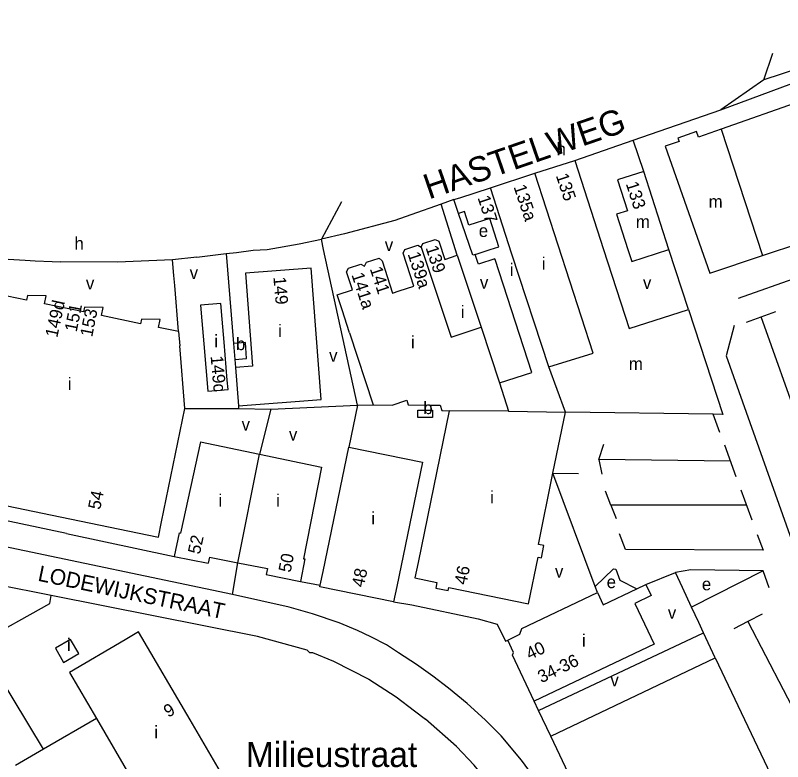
# Model space of a CAD drawing. Extents: x 157699 to 159683, y 381451 to 383293.
# Drawn here: x 159180.6 to 159425.3, y 382736.7 to 382974.7 of the extents above; entities that cross this region are included whole.
import ezdxf

# ---------------------------------------------------------------- set-up
doc = ezdxf.new("R2010")
doc.units = 0
for name, color, linetype in [('BLT_Basislijn', 7, 'Continuous'), ('BLT_Bebouwing', 7, 'Continuous'), ('BLT_Bebouwing_beschrifting', 7, 'Continuous'), ('BLT_Centroide', 7, 'Continuous'), ('BLT_Huisnummer', 7, 'Continuous'), ('BLT_Huisnummer_reeks', 7, 'Continuous'), ('BLT_Onderverdeling_panden', 7, 'Continuous'), ('BLT_Straatnaam', 7, 'Continuous'), ('BLT_Straatnaam_hoofdweg', 7, 'Continuous'), ('BLT_Vlakafsluiter', 7, 'Continuous')]:
    doc.layers.add(name, color=color, linetype=linetype)

msp = doc.modelspace()

# ---------------------------------------------------------------- linework, layer by layer
at = {"layer": 'BLT_Basislijn'}
for p, q in [((159405.59, 382944.56), (159433.38, 382954.9)), ((159419.3, 382954.14), (159405.59, 382944.56)), ((159377.66, 382934.89), (159405.59, 382944.56)), ((159358.99, 382928.43), (159377.66, 382934.89)), ((159381.06, 382924.92), (159377.66, 382934.89)), ((159316.43, 382914.45), (159306.72, 382911.03)), ((159320.48, 382915.92), (159316.43, 382914.45)), ((159321.51, 382898.15), (159316.43, 382914.45)), ((159271.08, 382901.86), (159278.18, 382903.33)), ((159395.3, 382880.89), (159389.05, 382899.99)), ((159238.5, 382897.55), (159230.71, 382896.67)), ((159238.5, 382897.55), (159247.77, 382898.73)), ((159247.77, 382898.73), (159251.13, 382899.05)), ((159247.77, 382898.73), (159250.17, 382870.05)), ((159411.28, 382884.48), (159430.54, 382891.32)), ((159232.61, 382873.85), (159231.39, 382888.49)), ((159418.48, 382878.56), (159423.16, 382880.28)), ((159413.8, 382876.85), (159418.48, 382878.56)), ((159444.29, 382805.9), (159418.48, 382878.56)), ((159250.58, 382864.94), (159250.77, 382862.38)), ((159289.75, 382850.37), (159294.66, 382850.46)), ((159234.65, 382849.3), (159251.75, 382849.31)), ((159251.72, 382850.16), (159251.75, 382849.31)), ((159251.75, 382849.31), (159262.09, 382849.15)), ((159262.09, 382849.15), (159258.5, 382834.72)), ((159262.09, 382849.15), (159289.75, 382850.37)), ((159289.75, 382850.37), (159286.99, 382837.02)), ((159405.33, 382841.71), (159403.13, 382847.47)), ((159366.66, 382833.1), (159368.33, 382837.98)), ((159410.49, 382827.48), (159406.9, 382837.58)), ((159408.69, 382832.53), (159366.66, 382833.1)), ((159366.66, 382833.1), (159367.7, 382828.4)), ((159352.07, 382828.68), (159360.16, 382828.55)), ((159365.53, 382792.56), (159352.07, 382828.68)), ((159370.57, 382818.5), (159368.87, 382823)), ((159415.56, 382813.69), (159412.12, 382823.31)), ((159413.84, 382818.5), (159370.57, 382818.5)), ((159370.57, 382818.5), (159372.2, 382814.21)), ((159249.82, 382790.04), (159157.68, 382809.27)), ((159249.82, 382790.04), (159251.53, 382800.15)), ((159381.72, 382793.17), (159391.11, 382797.04)), ((159393.35, 382792.24), (159391.11, 382797.04)), ((159419.07, 382797.56), (159396.27, 382785.95)), ((159421.07, 382792.13), (159419.07, 382797.56)), ((159271.49, 382794.17), (159277.85, 382792.96)), ((159192.02, 382789.67), (159172.64, 382793.53)), ((159366.25, 382790.62), (159365.53, 382792.56)), ((159396.27, 382785.95), (159393.35, 382792.24)), ((159267.9, 382785.97), (159249.82, 382790.04)), ((159398.56, 382781.04), (159396.27, 382785.95)), ((159418.75, 382783.71), (159414.23, 382781.36)), ((159400.07, 382777.8), (159398.56, 382781.04)), ((159414.23, 382781.36), (159409.71, 382779.02)), ((159414.23, 382781.36), (159441.99, 382727.89)), ((159347.48, 382753.01), (159400.07, 382777.8)), ((159403.79, 382769.82), (159400.07, 382777.8)), ((159189.49, 382740.66), (159169.07, 382774.57)), ((159347.48, 382753.01), (159346.07, 382755.99)), ((159307.89, 382752.96), (159311.44, 382750.26)), ((159351.37, 382744.8), (159347.48, 382753.01)), ((159206.41, 382750.47), (159189.49, 382740.66)), ((159189.49, 382740.66), (159180.65, 382735.54))]:
    msp.add_line(p, q, dxfattribs=at)
for points in [[(159482.05, 382974.66), (159419.3, 382954.14)], [(159306.72, 382911.03), (159301.59, 382909.22), (159285.55, 382904.97), (159278.18, 382903.33)], [(159327.25, 382898.44), (159326.49, 382898.2), (159321.91, 382911.53)], [(159251.13, 382899.05), (159256.38, 382899.84), (159260.85, 382900), (159271.08, 382901.86)], [(159289.75, 382850.37), (159278.9, 382900), (159278.18, 382903.33)], [(159174.06, 382897.31), (159178.29, 382896.96), (159183.66, 382896.59), (159186.91, 382896.41)], [(159186.91, 382896.41), (159192.29, 382896.17), (159194.9, 382896.09)], [(159230.71, 382896.67), (159213.14, 382896.01), (159194.9, 382896.09)], [(159231.39, 382888.49), (159231.13, 382891.69), (159230.71, 382896.67)], [(159409.89, 382875.79), (159407.36, 382866.13), (159430.53, 382800.86), (159435.45, 382802.6)], [(159196.92, 382809.44), (159162.12, 382816.84), (159164.52, 382828.13)], [(159196.92, 382809.44), (159231.19, 382802.16)], [(159417.25, 382809.12), (159419.08, 382804.13), (159375.19, 382804.37), (159373.3, 382809.31)], [(159365.53, 382792.56), (159371.42, 382798.18), (159372.14, 382798.11), (159373.36, 382794.55), (159378.78, 382791.77)], [(159419.07, 382797.56), (159396.05, 382797.87), (159391.11, 382797.04)], [(159169.07, 382774.57), (159191.56, 382787.19), (159192.02, 382789.67)], [(159274.43, 382771.53), (159273.7, 382772.23), (159257.81, 382776.61), (159192.02, 382789.67)], [(159301.24, 382787.64), (159307.05, 382786.68), (159328.25, 382782.21), (159334.31, 382780.6), (159336.95, 382775.15), (159337.62, 382775.47)], [(159330.47, 382750), (159324.69, 382755.29), (159318.76, 382760.18), (159313.79, 382763.99), (159308.48, 382767.72), (159302.77, 382771.4), (159298.94, 382773.91), (159294.01, 382776.56), (159289.75, 382778.54), (159283.84, 382780.98), (159275.31, 382783.83), (159267.9, 382785.97)], [(159274.43, 382771.53), (159275.35, 382771.52), (159282.09, 382768.77), (159293.32, 382763.04), (159302.06, 382757.38), (159307.89, 382752.96)], [(159328.36, 382733.92), (159326.98, 382735.56), (159321.31, 382741.52), (159311.44, 382750.26)], [(159371.1, 382685.16), (159365.19, 382697.64), (159361.34, 382705.19), (159358.24, 382711.23), (159354.7, 382717.43), (159350.72, 382724.13), (159346.42, 382731.2), (159342.06, 382737.2), (159335.54, 382744.96), (159330.47, 382750)]]:
    msp.add_lwpolyline(points, dxfattribs=at)
at = {"layer": 'BLT_Bebouwing'}
for p, q in [((159471.87, 382961.72), (159405.77, 382938.41)), ((159387.82, 382932.93), (159402.1, 382892.49)), ((159346.28, 382924.3), (159358.99, 382928.43)), ((159332.1, 382919.7), (159346.28, 382924.3)), ((159322.36, 382916.53), (159332.1, 382919.7)), ((159320.48, 382915.92), (159322.36, 382916.53)), ((159331.89, 382909.88), (159325.26, 382907.72)), ((159334.81, 382900.9), (159331.89, 382909.88)), ((159418.86, 382898.09), (159434.65, 382903.36)), ((159402.1, 382892.49), (159418.86, 382898.09)), ((159184.15, 382883.86), (159171.78, 382886.41)), ((159184.46, 382885.38), (159184.15, 382883.86)), ((159329.21, 382875.22), (159334.98, 382857.47)), ((159232.61, 382873.85), (159232.99, 382869.32)), ((159287.19, 382873.46), (159294.66, 382850.46)), ((159248.16, 382858.39), (159247.14, 382870.43)), ((159253.93, 382870.35), (159250.17, 382870.05)), ((159254.34, 382865.24), (159253.93, 382870.35)), ((159234.65, 382849.3), (159232.99, 382869.32)), ((159250.58, 382864.94), (159254.34, 382865.24)), ((159352.07, 382828.68), (159356.06, 382848.18)), ((159239.58, 382838.68), (159233.29, 382809.56)), ((159239.58, 382838.68), (159258.5, 382834.72)), ((159258.5, 382834.72), (159278.19, 382830.63)), ((159278.19, 382830.63), (159272.45, 382801.43)), ((159169.6, 382819.99), (159197.9, 382814.15)), ((159197.9, 382814.15), (159226.2, 382808.31)), ((159232.81, 382809.64), (159231.19, 382802.16)), ((159232.81, 382809.64), (159233.29, 382809.56)), ((159231.19, 382802.16), (159242.05, 382800.01)), ((159242.47, 382801.95), (159242.05, 382800.01)), ((159242.47, 382801.95), (159251.53, 382800.15)), ((159251.53, 382800.15), (159261.02, 382798.26)), ((159272.92, 382801.35), (159271.49, 382794.17)), ((159272.45, 382801.43), (159272.92, 382801.35)), ((159261.02, 382798.26), (159260.6, 382796.34)), ((159260.6, 382796.34), (159271.49, 382794.17)), ((159277.74, 382792.46), (159277.85, 382792.96)), ((159301.24, 382787.64), (159277.74, 382792.46)), ((159378.78, 382791.77), (159381.72, 382793.17)), ((159384.35, 382774.19), (159346.07, 382755.99)), ((159351.37, 382744.8), (159403.79, 382769.82)), ((159206.41, 382750.47), (159219.18, 382728.66)), ((159379.52, 382685.92), (159351.37, 382744.8))]:
    msp.add_line(p, q, dxfattribs=at)
for points in [[(159405.77, 382938.41), (159398.5, 382935.85), (159397.9, 382937.59), (159391.95, 382935.48), (159392.28, 382934.49), (159387.82, 382932.93)], [(159358.99, 382928.43), (159368.23, 382900), (159376.42, 382874.78), (159395.3, 382880.89)], [(159381.06, 382924.92), (159372.67, 382922.21), (159375.82, 382912.33), (159372.35, 382911.22)], [(159389.05, 382899.99), (159381.06, 382924.92)], [(159321.91, 382911.53), (159320.48, 382915.92)], [(159325.26, 382907.72), (159323.82, 382912.15), (159321.91, 382911.53)], [(159372.35, 382911.22), (159375.99, 382900), (159377.25, 382896.15), (159389.05, 382899.99)], [(159310.06, 382900.8), (159310.59, 382901.94), (159314.47, 382903.21), (159315.67, 382902.62), (159317.57, 382896.85), (159321.51, 382898.15)], [(159304.24, 382898.84), (159304.84, 382900.04), (159308.93, 382901.38), (159310.06, 382900.8)], [(159327.25, 382898.44), (159332.05, 382900), (159334.81, 382900.9)], [(159283.26, 382885.55), (159288.09, 382887.11), (159286.22, 382892.86), (159286.83, 382894.06), (159290.72, 382895.32), (159291.99, 382894.68), (159292.63, 382895.92), (159296.65, 382897.23), (159297.54, 382896.43), (159300.89, 382886.11), (159303.05, 382886.82)], [(159303.05, 382886.82), (159307.66, 382888.31), (159304.24, 382898.84)], [(159321.51, 382898.15), (159329.21, 382875.22)], [(159333.61, 382896.77), (159333.52, 382897.06), (159328.26, 382895.35), (159328.08, 382895.89), (159327.25, 382898.44)], [(159334.98, 382857.47), (159345.29, 382860.82), (159333.61, 382896.77)], [(159251.72, 382850.16), (159278.12, 382852.23), (159274.88, 382894.07), (159254, 382892.47), (159256.24, 382862.81), (159250.77, 382862.38)], [(159232.61, 382873.85), (159226.2, 382875.17), (159226.72, 382877.69), (159220.8, 382877.76), (159220.49, 382876.35), (159208.01, 382878.93), (159208.53, 382881.46), (159202.62, 382881.62), (159202.33, 382880.11), (159189.86, 382882.68), (159190.37, 382885.19), (159184.46, 382885.38)], [(159287.19, 382873.46), (159284.81, 382880.79), (159283.26, 382885.55)], [(159247.14, 382870.43), (159246.51, 382877.81), (159246.08, 382882.79), (159239.6, 382882.22)], [(159239.6, 382882.22), (159240.02, 382877.24), (159240.65, 382869.94)], [(159395.3, 382880.89), (159406.24, 382847.42), (159403.13, 382847.47)], [(159250.17, 382870.05), (159250.58, 382864.94)], [(159240.65, 382869.94), (159241.94, 382854.83), (159248.42, 382855.37), (159248.16, 382858.39)], [(159250.77, 382862.38), (159251.72, 382850.16)], [(159294.66, 382850.46), (159300.72, 382850.4), (159305.4, 382851.93), (159305.89, 382850.44), (159313.32, 382850.37)], [(159226.2, 382808.31), (159227.21, 382813.21), (159234.65, 382849.3)], [(159318.9, 382848.6), (159309.01, 382800.18), (159308, 382795.28), (159315.06, 382793.82), (159314.71, 382792.05), (159318.64, 382791.25), (159318.86, 382792.26), (159344.3, 382786.99), (159347.34, 382801.91), (159348.38, 382801.69), (159349.18, 382805.62), (159347.42, 382806), (159352.07, 382828.68)], [(159313.32, 382850.37), (159316.04, 382850.34), (159316.6, 382848.63), (159318.9, 382848.6)], [(159403.13, 382847.47), (159356.06, 382848.18)], [(159277.85, 382792.96), (159278.76, 382797.35), (159286.99, 382837.02)], [(159286.99, 382837.02), (159310.47, 382832.21), (159302.26, 382792.53), (159301.24, 382787.64)], [(159366.25, 382790.62), (159368.11, 382786.7), (159378.78, 382791.77)], [(159381.72, 382793.17), (159383.4, 382789.66), (159378.17, 382787.19), (159384.35, 382774.19)], [(159342.18, 382779.13), (159366.25, 382790.62)], [(159229.92, 382710.31), (159251.98, 382723.22), (159236.3, 382750), (159219.86, 382778.09), (159215.55, 382775.56), (159197.8, 382765.18), (159206.41, 382750.47)], [(159337.62, 382775.47), (159341.54, 382777.35), (159342.18, 382779.13)], [(159193.32, 382772.9), (159195.97, 382768.37), (159200.78, 382771.19), (159198.13, 382775.71), (159193.32, 382772.9)], [(159346.07, 382755.99), (159339.15, 382770.62), (159339.49, 382771.54), (159337.62, 382775.47)], [(159403.79, 382769.82), (159431.91, 382710.87)]]:
    msp.add_lwpolyline(points, dxfattribs=at)
msp.add_lwpolyline([(159308.96, 382848.77), (159313.59, 382848.77), (159313.59, 382846.4), (159308.96, 382846.4)], close=True, dxfattribs=at)
at = {"layer": 'BLT_Onderverdeling_panden'}
for p, q in [((159405.77, 382938.41), (159418.86, 382898.09)), ((159334.98, 382857.47), (159337.89, 382848.5)), ((159337.89, 382848.5), (159318.9, 382848.6)), ((159337.89, 382848.5), (159356.06, 382848.18)), ((159251.53, 382800.15), (159258.5, 382834.72))]:
    msp.add_line(p, q, dxfattribs=at)
for points in [[(159350.77, 382862.57), (159364.86, 382866.99), (159346.28, 382924.3)], [(159338.97, 382898.53), (159332.1, 382919.7)], [(159310.06, 382900.8), (159319.55, 382872.08), (159329.21, 382875.22)], [(159350.77, 382862.57), (159338.97, 382898.53)], [(159356.06, 382848.18), (159350.77, 382862.57)]]:
    msp.add_lwpolyline(points, dxfattribs=at)
at = {"layer": 'BLT_Vlakafsluiter'}
for p, q in [((159419.3, 382954.14), (159422.17, 382962.56)), ((159284.62, 382915.23), (159278.18, 382903.33))]:
    msp.add_line(p, q, dxfattribs=at)

# ---------------------------------------------------------------- texts
at = {"layer": 'BLT_Bebouwing_beschrifting'}
msp.add_text('Milieustraat', height=8, rotation=359.9999, dxfattribs=at).set_placement((159254.09, 382735))
at = {"layer": 'BLT_Centroide'}
for s, p in [('h', (159353.21, 382930.02)), ('m', (159401.73, 382913.29)), ('m', (159378.51, 382906.88)), ('e', (159328.4, 382904)), ('h', (159199.41, 382899.94)), ('v', (159298.42, 382899.51)), ('i', (159348.48, 382893.53)), ('i', (159338.27, 382891.56)), ('v', (159236.18, 382890.62)), ('v', (159203.08, 382887.27)), ('v', (159328.77, 382887.5)), ('v', (159380.78, 382887.46)), ('i', (159322.64, 382878.12)), ('i', (159264.41, 382872.09)), ('i', (159244.02, 382868.8)), ('i', (159306.75, 382868.46)), ('b', (159250.95, 382867.92)), ('v', (159280.65, 382864.21)), ('m', (159376.27, 382861.58)), ('i', (159197.3, 382855.17)), ('b', (159310.69, 382847.53)), ('v', (159252.74, 382842.28)), ('v', (159267.84, 382839.09)), ('i', (159245.35, 382817.99)), ('i', (159263.73, 382817.99)), ('i', (159332.03, 382819.03)), ('i', (159294.11, 382812.33)), ('v', (159352.71, 382795.41)), ('e', (159369.2, 382792.03)), ('e', (159399.57, 382791.34)), ('v', (159388.72, 382782.26)), ('i', (159361.34, 382773.34)), ('i', (159197.05, 382772.03)), ('v', (159370.39, 382760.74)), ('i', (159224.89, 382744.2))]:
    msp.add_text(s, height=4, dxfattribs=at).set_placement(p)
at = {"layer": 'BLT_Huisnummer'}
for s, rotation, p in [('135', 288.4495, (159352.93, 382923.57)), ('133', 288.0002, (159375.25, 382920.97)), ('135a', 288.4495, (159339.46, 382920)), ('137', 288.003, (159327.96, 382916.54)), ('139', 288.0026, (159311.39, 382900.59)), ('149', 275.0077, (159262.86, 382891.19)), ('149c', 275.0077, (159242.84, 382866.02)), ('46', 78.5122, (159324.46, 382792.92)), ('48', 78.3074, (159291.72, 382792.1)), ('9', 30.3348, (159229.34, 382750.66))]:
    msp.add_text(s, height=4, rotation=rotation, dxfattribs=at).set_placement(p)
at = {"layer": 'BLT_Huisnummer_reeks'}
for s, rotation, p in [('139a', 288.0026, (159305.66, 382898.56)), ('141a', 288.0026, (159287.74, 382891.97)), ('141', 288.0026, (159293.59, 382893.89)), ('149d', 77.7509, (159193.92, 382871.72)), ('151', 78.7509, (159200.13, 382873.54)), ('153', 78.7509, (159205.07, 382871.93)), ('54', 78.3455, (159207.6, 382816.85)), ('52', 77.8202, (159239.43, 382802.64)), ('50', 78.866, (159268.36, 382796.83)), ('40', 25.7029, (159344.65, 382769.08)), ('34-36', 25.7029, (159348.38, 382761.68))]:
    msp.add_text(s, height=4, rotation=rotation, dxfattribs=at).set_placement(p)
at = {"layer": 'BLT_Straatnaam'}
msp.add_text('LODEWIJKSTRAAT', height=5, rotation=348.288, dxfattribs=at).set_placement((159187.49, 382794.43))
at = {"layer": 'BLT_Straatnaam_hoofdweg'}
msp.add_text('HASTELWEG', height=8, rotation=19.0495, dxfattribs=at).set_placement((159312.48, 382915.91))

doc.saveas('drawing.dxf')
